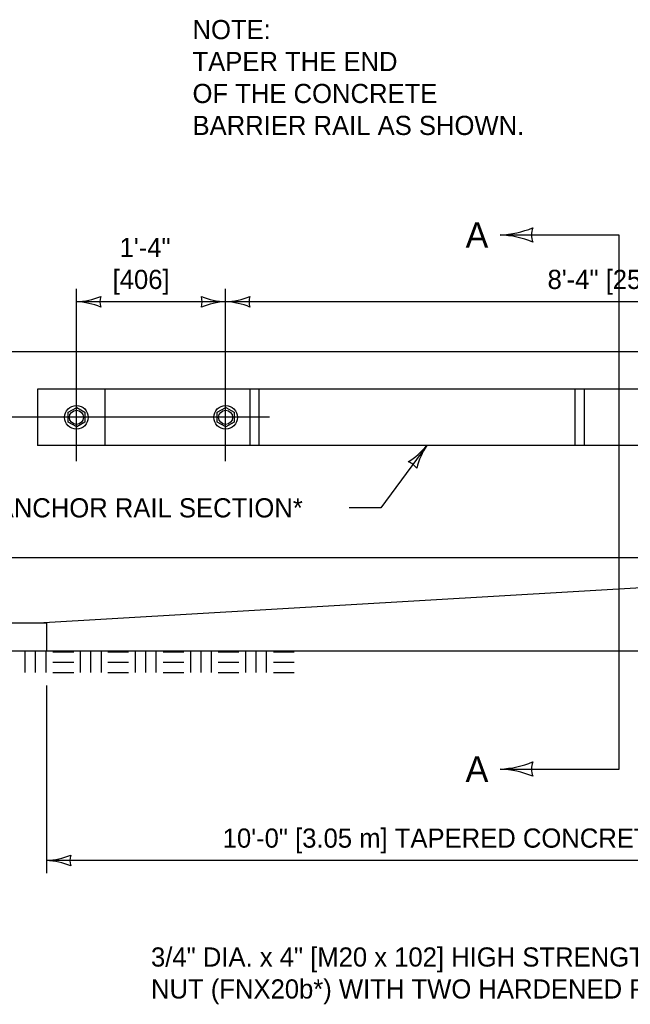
# Model space of a CAD drawing. Extents: x 49983 to 50021, y 49963.5 to 50011.4.
# Drawn here: x 50001.507 to 50003.419, y 49993.361 to 49996.443 of the extents above; entities that cross this region are included whole.
import ezdxf

# ---------------------------------------------------------------- set-up
doc = ezdxf.new("R2010")
doc.units = 0
for name, color, linetype in [('Level 1', 7, 'Continuous'), ('Level 10', 7, 'Continuous'), ('Level 2', 7, 'Continuous'), ('Level 3', 7, 'Continuous'), ('Level 4', 7, 'Continuous'), ('Level 5', 7, 'Continuous'), ('Level 6', 7, 'Continuous')]:
    doc.layers.add(name, color=color, linetype=linetype)

msp = doc.modelspace()

# ---------------------------------------------------------------- linework, layer by layer
at = {"layer": 'Level 1'}
for p, q in [((50004.7024, 49995.4035), (50000.7665, 49995.4035)), ((50001.5623, 49995.2862), (50001.5623, 49995.1105)), ((50005.4515, 49995.2862), (50001.5623, 49995.2862)), ((50001.7736, 49995.2862), (50001.7736, 49995.1105)), ((50002.2274, 49995.2862), (50002.2274, 49995.1105)), ((50003.2457, 49995.2862), (50003.2457, 49995.1105)), ((50001.6582, 49995.214), (50001.6855, 49995.2289)), ((50001.6582, 49995.183), (50001.6582, 49995.214)), ((50001.6855, 49995.2289), (50001.711, 49995.214)), ((50001.711, 49995.214), (50001.711, 49995.183)), ((50002.1256, 49995.214), (50002.1529, 49995.2289)), ((50002.1256, 49995.183), (50002.1256, 49995.214)), ((50002.1529, 49995.2289), (50002.1783, 49995.214)), ((50002.1783, 49995.214), (50002.1783, 49995.183)), ((50001.6855, 49995.1681), (50001.6582, 49995.183)), ((50001.711, 49995.183), (50001.6855, 49995.1681)), ((50002.1529, 49995.1681), (50002.1256, 49995.183)), ((50002.1783, 49995.183), (50002.1529, 49995.1681)), ((50005.456, 49995.1105), (50001.5623, 49995.1105)), ((50005.0789, 49994.7591), (50000.7665, 49994.7591)), ((50005.0789, 49994.7591), (50001.565, 49994.5542)), ((50001.5908, 49994.5542), (50000.7665, 49994.5542)), ((50001.5908, 49994.5542), (50001.5908, 49994.4663)), ((50005.1046, 49994.4663), (50000.7665, 49994.4663)), ((50001.5243, 49994.3996), (50001.5243, 49994.4646)), ((50001.5568, 49994.3996), (50001.5568, 49994.4646)), ((50001.5893, 49994.3996), (50001.5893, 49994.4646)), ((50001.6109, 49994.4646), (50001.676, 49994.4646)), ((50001.6977, 49994.3996), (50001.6977, 49994.4646)), ((50001.7301, 49994.3996), (50001.7301, 49994.4646)), ((50001.7626, 49994.3996), (50001.7626, 49994.4646)), ((50001.7829, 49994.4645), (50001.8479, 49994.4645)), ((50001.8696, 49994.3995), (50001.8696, 49994.4645)), ((50001.9021, 49994.3995), (50001.9021, 49994.4645)), ((50001.9346, 49994.3995), (50001.9346, 49994.4645)), ((50001.9562, 49994.4645), (50002.0213, 49994.4645)), ((50002.043, 49994.3995), (50002.043, 49994.4645)), ((50002.0754, 49994.3995), (50002.0754, 49994.4645)), ((50002.1079, 49994.3995), (50002.1079, 49994.4645)), ((50002.1285, 49994.4643), (50002.1935, 49994.4643)), ((50002.2152, 49994.3993), (50002.2152, 49994.4643)), ((50002.2477, 49994.3993), (50002.2477, 49994.4643)), ((50002.2802, 49994.3993), (50002.2802, 49994.4643)), ((50002.3018, 49994.4643), (50002.3669, 49994.4643)), ((50001.6109, 49994.4321), (50001.676, 49994.4321)), ((50001.7829, 49994.432), (50001.8479, 49994.432)), ((50001.9562, 49994.432), (50002.0213, 49994.432)), ((50002.1285, 49994.4318), (50002.1935, 49994.4318)), ((50002.3018, 49994.4318), (50002.3669, 49994.4318)), ((50001.6109, 49994.3996), (50001.676, 49994.3996)), ((50001.7829, 49994.3995), (50001.8479, 49994.3995)), ((50001.9562, 49994.3995), (50002.0213, 49994.3995)), ((50002.1285, 49994.3993), (50002.1935, 49994.3993)), ((50002.3018, 49994.3993), (50002.3669, 49994.3993))]:
    msp.add_line(p, q, dxfattribs=at)
for centre in [(50001.6845, 49995.1984), (50002.1518, 49995.1984)]:
    msp.add_circle(centre, 0.037, dxfattribs=at)
at = {"layer": 'Level 10'}
msp.add_line((50002.2558, 49995.2862), (50002.2558, 49995.1105), dxfattribs=at)
at = {"layer": 'Level 3'}
for p, q in [((50002.1518, 49995.56), (50001.6845, 49995.56)), ((50004.6482, 49995.56), (50002.1518, 49995.56)), ((50001.5908, 49994.3596), (50001.5908, 49993.7716)), ((50005.0789, 49993.8116), (50001.5908, 49993.8116))]:
    msp.add_line(p, q, dxfattribs=at)
msp.add_lwpolyline([(50002.7817, 49995.1105), (50002.6382, 49994.9151), (50002.5382, 49994.9151)], dxfattribs=at)
for centre, radius, start, end in [((50002.9965, 49996.0792), 0.3107, 272.8273, 292.0772), ((50003.1828, 49995.7689), 0.073, 162.1388, 197.8612), ((50002.9997, 49995.4728), 0.2964, 67.456, 87.6395), ((50001.673, 49995.7928), 0.233, 272.8273, 292.0772), ((50001.8127, 49995.56), 0.0548, 162.1388, 197.8612), ((50002.161, 49995.7822), 0.2223, 247.456, 267.6395), ((50002.0236, 49995.56), 0.0548, 342.1388, 17.8612), ((50002.1403, 49995.7928), 0.233, 272.8273, 292.0772), ((50002.2801, 49995.56), 0.0548, 162.1388, 197.8612), ((50001.6753, 49995.3379), 0.2223, 67.456, 87.6395), ((50002.1633, 49995.3273), 0.233, 92.8273, 112.0772), ((50002.1427, 49995.3379), 0.2223, 67.456, 87.6395), ((50002.608, 49995.2493), 0.2223, 301.1755, 321.359), ((50002.976, 49994.9821), 0.233, 146.5468, 165.7966), ((50002.7058, 49995.0072), 0.0548, 35.8583, 71.5807), ((50002.9965, 49994.4079), 0.3107, 272.8273, 292.0772), ((50002.9997, 49993.8014), 0.2964, 67.456, 87.6395), ((50003.1828, 49994.0976), 0.073, 162.1388, 197.8612), ((50001.5793, 49994.0443), 0.233, 272.8273, 292.0772), ((50001.719, 49993.8116), 0.0548, 162.1388, 197.8612), ((50001.5816, 49993.5894), 0.2223, 67.456, 87.6395)]:
    msp.add_arc(centre, radius, start, end, dxfattribs=at)
at = {"layer": 'Level 4'}
msp.add_line((50003.275, 49995.2862), (50003.275, 49995.1105), dxfattribs=at)
for centre in [(50001.6845, 49995.1984), (50002.1518, 49995.1984)]:
    msp.add_circle(centre, 0.022, dxfattribs=at)
at = {"layer": 'Level 5'}
for p, q in [((50001.6845, 49995.0614), (50001.6845, 49995.6)), ((50002.1518, 49995.0614), (50002.1518, 49995.6)), ((50002.2888, 49995.1984), (50001.2155, 49995.1984))]:
    msp.add_line(p, q, dxfattribs=at)
at = {"layer": 'Level 6'}
msp.add_line((50003.3841, 49995.7689), (50003.0119, 49995.7689), dxfattribs=at)
msp.add_lwpolyline([(50003.0119, 49994.0976), (50003.3841, 49994.0976), (50003.3841, 49995.7689)], dxfattribs=at)

# ---------------------------------------------------------------- texts
at = {"layer": 'Level 2'}
for s, height, p in [('NOTE:', 0.06, (50002.0481, 49996.3818)), ('TAPER THE END ', 0.06, (50002.0481, 49996.2818)), ('OF THE CONCRETE', 0.06, (50002.0481, 49996.1818)), ('BARRIER RAIL AS SHOWN.', 0.06, (50002.0481, 49996.0818)), ('A', 0.08, (50002.9032, 49995.7289)), ('1\'-4"', 0.06, (50001.8197, 49995.7)), ('[406]', 0.06, (50001.7979, 49995.6)), ('8\'-4" [2540]', 0.06, (50003.1599, 49995.6)), ('ANCHOR RAIL SECTION*', 0.06, (50001.4349, 49994.8851)), ('A', 0.08, (50002.9032, 49994.0576)), ('10\'-0" [3.05 m] TAPERED CONCRETE BRIDGE RAIL **', 0.06, (50002.1426, 49993.8516)), ('3/4" DIA. x 4" [M20 x 102] HIGH STRENGTH HEX BOLT (FBX20b*) AND', 0.06, (50001.9181, 49993.4795)), ('NUT (FNX20b*) WITH TWO HARDENED FLAT WASHERS (FWC20b*) (TYP.)', 0.06, (50001.9181, 49993.3795))]:
    msp.add_text(s, height=height, dxfattribs=at).set_placement(p)

doc.saveas('drawing.dxf')
